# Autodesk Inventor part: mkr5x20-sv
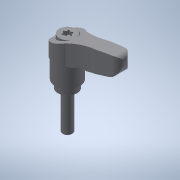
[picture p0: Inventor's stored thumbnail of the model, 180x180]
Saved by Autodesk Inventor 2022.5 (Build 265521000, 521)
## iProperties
Created: 2017-09
Part Number: mkr5x20-sv
Material: 一般
Document SubType Name: Modeling
Designer: imaocorp
Density: 1 g/cm^3
Appearance: 既定
Author: imaocorp
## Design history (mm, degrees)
node "mkr5x20-sv.x_t1"
node "mkr5x20-sv"
node "Base1"
